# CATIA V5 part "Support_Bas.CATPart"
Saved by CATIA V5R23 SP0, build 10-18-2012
Part number: Support_Bas
Material "Aluminium": density 2710 kg/m3, Young's modulus 7e+10 Pa, Poisson ratio 0.346, thermal expansion 2.36e-05 1/K
Bounding box of the stored display mesh (mm): x -45 to 45, y 0 to 70, z -7.5 to 7.5
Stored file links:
  P:\eleve\Support_Bas.CATPart
  C:\Program Files\Dassault Systemes\B23\win_b64\startup\materials\French\Catalog.CATMaterial
  d:\catia_soft\intel_a\reffiles\standard\MetricThickPitch.txt
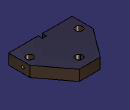
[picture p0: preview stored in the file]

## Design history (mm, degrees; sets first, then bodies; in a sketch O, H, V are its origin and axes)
Body1 (main body)
  Sketch1 on xy-plane, origin (0, 0, 0), H (1, 0, 0), V (0, 1, 0)
    point P1 (-45, 0)
    line L1 (-45, 0) -> (45, 0)
    line L2 (45, 0) -> (45, 30)
    point P3 (45, 30)
    line L3 (45, 30) -> (15, 70)
    point P4 (15, 70)
    line L4 (15, 70) -> (-15, 70)
    point P5 (-15, 70)
    line L5 (-15, 70) -> (-45, 30)
    line L6 (-45, 30) -> (-45, 0)
    reference intersected line E1 through (0, 0) direction (0, 1) from yz-plane
    reference intersected line E2 through (0, 0) direction (0, 1) from yz-plane
    reference intersected line E3 through (0, 0) direction (-1, 0) from zx-plane
    distance L6 L2 = 90
    distance E3 L4 = 70
    distance L2 P4 = 30
    distance P3 L4 = 40
    coincidence: P1 H
    horizontal: L1 H, L4 H
    vertical: L2 V, L6 V
    symmetry: L6 L2 E1, P4 P5 E2, L3 L5 V
  Pad1: profile Sketch1, direction (0, 0, 1), length 7.5, mirrored extent
  Sketch2 "Esquisse.2" on face of Pad1, origin (-2.0176, 52.3359, -7.5), H (1, 0, 0), V (0, -1, 0)
    point P1 (2.0176, -2.6641)
    reference intersected line E1 through (2.0176, 0) direction (0, 1) from yz-plane
    reference intersected line E2 (-42.9824, 52.3359) -> (47.0176, 52.3359) from face of Pad1
    distance E2 P1 = 55
    coincidence: P1 E1
  Hole1 "Trou.1": placed by Sketch2, at (0, 55, -7.5) direction (0, 0, 1), diameter 10, through (limit type 3)
  Sketch3 "Esquisse.3" on xy-plane, origin (0, 0, 0), H (1, 0, 0), V (0, 1, 0)
    line L1 (-3, -4) -> (3, -4)
    line L2 (3, -4) -> (3, 6)
    line L3 (3, 6) -> (-3, 6)
    line L4 (-3, 6) -> (-3, -4)
    reference intersected line E1 through (0, 0) direction (0, 1) from yz-plane
    reference intersected line E2 (45, 0) -> (-45, 0) from face of Pad1
    distance L4 L2 = 6
    distance L3 E2 = 6
    distance L1 H = 4
    horizontal: L1 H, L3 H
    vertical: L2 V, L4 V
    symmetry: L4 L2 E1
  Pocket1: profile Sketch3, direction (0, 0, -1), through (limit type 3), opposite side through (limit type 3)
  Sketch4 "Esquisse.4" on face of Pad1, origin (-33.8023, 0, -1.5862), H (1, 0, 0), V (0, 0, 1)
    point P1 (-1.1977, 1.5862)
    reference intersected line E1 through (0, 1.5862) direction (-1, 0) from xy-plane
    reference intersected line E2 through (33.8023, 0) direction (0, 1) from yz-plane
    distance P1 E2 = 35
    coincidence: P1 E1
  Hole2 "Trou.2": placed by Sketch4, at (-35, 0, 0) direction (0, 1, 0), diameter 4.134, depth 12, V-bottom angle 120, threaded "M5", thread diameter 5, thread depth 10, pitch 0.8
  Mirror1 "Symétrie.1": of Hole2, about yz-plane
  Sketch5 "Esquisse.5" on face of Pad1, origin (45, 13.6758, 1.3195), H (0, 1, 0), V (0, 0, 1)
    point P1 (6.3242, -1.3195)
    reference intersected line E1 (-13.6758, 6.1805) -> (16.3242, 6.1805) from face of Pad1
    reference intersected line E2 (16.3242, -8.8195) -> (-13.6758, -8.8195) from face of Pad1
    reference intersected line E3 (-13.6758, -8.8195) -> (-13.6758, 6.1805) from face of Pad1
    distance P1 E3 = 20
    equidistance: E1 E2 P1
  Hole3 "Trou.3": placed by Sketch5, at (45, 20, 0) direction (-1, 0, 0), diameter 4.134, depth 12, V-bottom angle 120, threaded "M5", thread diameter 5, thread depth 10, pitch 0.8
  Mirror2 "Symétrie.2": of Hole3, about yz-plane
  Sketch6 "Esquisse.6" on face of Pad1, origin (-28.4368, 18.1691, 7.5), H (1, 0, 0), V (0, 1, 0)
    point P1 (-6.5632, 1.8309)
    reference projected line E1 through (-6.5632, 0) direction (0, 1) from axis of face of Hole2
    reference projected line E2 through (0, 1.8309) direction (1, 0) from axis of face of Mirror2
    coincidence: P1 E1, P1 E2
  Hole4 "Trou.4": placed by Sketch6, at (-35, 20, 7.5) direction (0, 0, -1), diameter 10, through (limit type 3)
  Mirror3 "Symétrie.3": of Hole4, about yz-plane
